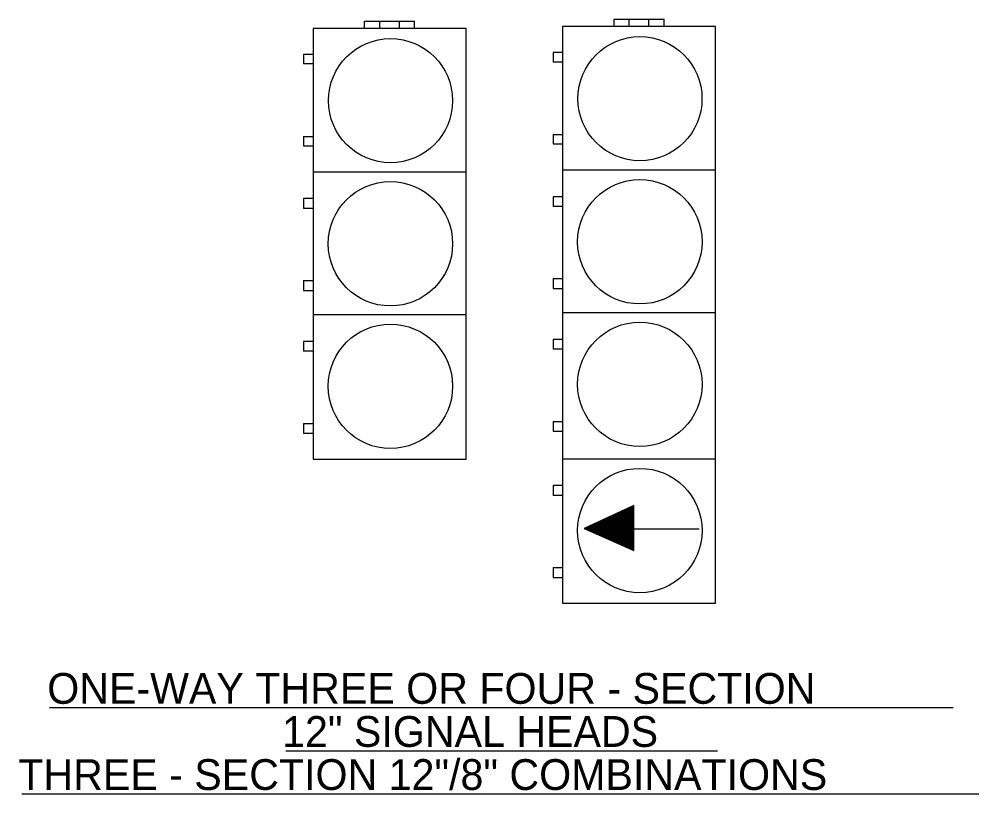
# Model space of a CAD drawing. Extents: x -1316.3 to -1303.1, y 2853.3 to 2863.3.
# Drawn here: x -1316.17 to -1313.052, y 2860.306 to 2862.823 of the extents above; entities that cross this region are included whole.
import ezdxf

# ---------------------------------------------------------------- set-up
doc = ezdxf.new("R2010")
doc.units = 0
for name, color, linetype in [('DETL-DIMS', 7, 'Continuous'), ('DETL-LINE', 7, 'Continuous'), ('DETL-TITL', 7, 'Continuous')]:
    doc.layers.add(name, color=color, linetype=linetype)

msp = doc.modelspace()

# ---------------------------------------------------------------- linework, layer by layer
at = {"layer": 'DETL-DIMS'}
for p, q in [((-1314.1736, 2861.2434), (-1314.3352, 2861.1682)), ((-1314.1856, 2861.1018), (-1314.1856, 2861.2378)), ((-1314.1832, 2861.1002), (-1314.1832, 2861.2386)), ((-1314.1808, 2861.0994), (-1314.1808, 2861.2402)), ((-1314.1784, 2861.0986), (-1314.1784, 2861.241)), ((-1314.176, 2861.097), (-1314.176, 2861.2426)), ((-1314.1736, 2861.0962), (-1314.1736, 2861.2434)), ((-1314.1736, 2861.0962), (-1314.1736, 2861.2434)), ((-1314.2528, 2861.1314), (-1314.2528, 2861.2066)), ((-1314.2504, 2861.1306), (-1314.2504, 2861.2074)), ((-1314.248, 2861.1298), (-1314.248, 2861.209)), ((-1314.2456, 2861.1282), (-1314.2456, 2861.2098)), ((-1314.2432, 2861.1274), (-1314.2432, 2861.2106)), ((-1314.2408, 2861.1266), (-1314.2408, 2861.2122)), ((-1314.2384, 2861.125), (-1314.2384, 2861.213)), ((-1314.236, 2861.1242), (-1314.236, 2861.2146)), ((-1314.2336, 2861.1234), (-1314.2336, 2861.2154)), ((-1314.2312, 2861.1218), (-1314.2312, 2861.2162)), ((-1314.2288, 2861.121), (-1314.2288, 2861.2178)), ((-1314.2264, 2861.1202), (-1314.2264, 2861.2186)), ((-1314.224, 2861.1186), (-1314.224, 2861.2202)), ((-1314.2216, 2861.1178), (-1314.2216, 2861.221)), ((-1314.2192, 2861.117), (-1314.2192, 2861.2218)), ((-1314.2168, 2861.1154), (-1314.2168, 2861.2234)), ((-1314.2144, 2861.1146), (-1314.2144, 2861.2242)), ((-1314.212, 2861.113), (-1314.212, 2861.2258)), ((-1314.2096, 2861.1122), (-1314.2096, 2861.2266)), ((-1314.2072, 2861.1114), (-1314.2072, 2861.2274)), ((-1314.2048, 2861.1106), (-1314.2048, 2861.229)), ((-1314.2024, 2861.109), (-1314.2024, 2861.2298)), ((-1314.2, 2861.1082), (-1314.2, 2861.2314)), ((-1314.1976, 2861.1066), (-1314.1976, 2861.2322)), ((-1314.1952, 2861.1058), (-1314.1952, 2861.233)), ((-1314.1928, 2861.105), (-1314.1928, 2861.2346)), ((-1314.1904, 2861.1034), (-1314.1904, 2861.2354)), ((-1314.188, 2861.1026), (-1314.188, 2861.237)), ((-1314.32, 2861.1618), (-1314.32, 2861.1754)), ((-1314.3176, 2861.1602), (-1314.3176, 2861.1762)), ((-1314.3152, 2861.1594), (-1314.3152, 2861.177)), ((-1314.3128, 2861.1586), (-1314.3128, 2861.1786)), ((-1314.3104, 2861.157), (-1314.3104, 2861.1794)), ((-1314.308, 2861.1562), (-1314.308, 2861.181)), ((-1314.3056, 2861.1554), (-1314.3056, 2861.1818)), ((-1314.3032, 2861.1538), (-1314.3032, 2861.1826)), ((-1314.3008, 2861.153), (-1314.3008, 2861.1842)), ((-1314.2984, 2861.1522), (-1314.2984, 2861.185)), ((-1314.296, 2861.1506), (-1314.296, 2861.1866)), ((-1314.2936, 2861.1498), (-1314.2936, 2861.1874)), ((-1314.2912, 2861.149), (-1314.2912, 2861.1882)), ((-1314.2888, 2861.1474), (-1314.2888, 2861.1898)), ((-1314.2864, 2861.1466), (-1314.2864, 2861.1906)), ((-1314.284, 2861.1458), (-1314.284, 2861.1922)), ((-1314.2816, 2861.1442), (-1314.2816, 2861.193)), ((-1314.2792, 2861.1434), (-1314.2792, 2861.1938)), ((-1314.2768, 2861.1426), (-1314.2768, 2861.1954)), ((-1314.2744, 2861.141), (-1314.2744, 2861.1962)), ((-1314.272, 2861.1402), (-1314.272, 2861.1978)), ((-1314.2696, 2861.1394), (-1314.2696, 2861.1986)), ((-1314.2672, 2861.1378), (-1314.2672, 2861.1994)), ((-1314.2648, 2861.137), (-1314.2648, 2861.201)), ((-1314.2624, 2861.1362), (-1314.2624, 2861.2018)), ((-1314.26, 2861.1346), (-1314.26, 2861.2034)), ((-1314.2576, 2861.1338), (-1314.2576, 2861.2042)), ((-1314.2552, 2861.133), (-1314.2552, 2861.205)), ((-1314.3352, 2861.1682), (-1314.1736, 2861.0962)), ((-1314.3344, 2861.1682), (-1314.3344, 2861.1682)), ((-1314.332, 2861.1666), (-1314.332, 2861.1698)), ((-1314.3296, 2861.1658), (-1314.3296, 2861.1706)), ((-1314.3272, 2861.165), (-1314.3272, 2861.1714)), ((-1314.3248, 2861.1634), (-1314.3248, 2861.173)), ((-1314.3224, 2861.1626), (-1314.3224, 2861.1738)), ((-1313.9608, 2861.1658), (-1314.3032, 2861.1658))]:
    msp.add_line(p, q, dxfattribs=at)
at = {"layer": 'DETL-LINE'}
for p, q in [((-1315.048, 2862.817), (-1314.8856, 2862.817)), ((-1315.048, 2862.793), (-1315.048, 2862.817)), ((-1314.9984, 2862.793), (-1314.9984, 2862.817)), ((-1314.9352, 2862.793), (-1314.9352, 2862.817)), ((-1314.8856, 2862.793), (-1314.8856, 2862.817)), ((-1314.4048, 2862.7994), (-1314.4048, 2860.925)), ((-1313.908, 2862.7994), (-1314.4048, 2862.7994)), ((-1314.2376, 2862.8234), (-1314.0752, 2862.8234)), ((-1314.2376, 2862.7994), (-1314.2376, 2862.8234)), ((-1314.188, 2862.7994), (-1314.188, 2862.8234)), ((-1314.1248, 2862.7994), (-1314.1248, 2862.8234)), ((-1314.0752, 2862.7994), (-1314.0752, 2862.8234)), ((-1313.908, 2860.925), (-1313.908, 2862.7994)), ((-1315.2152, 2862.793), (-1315.2152, 2861.3938)), ((-1314.7184, 2862.793), (-1315.2152, 2862.793)), ((-1314.7184, 2861.3938), (-1314.7184, 2862.793)), ((-1315.2152, 2862.709), (-1315.2464, 2862.709)), ((-1315.2464, 2862.709), (-1315.2464, 2862.6778)), ((-1314.4048, 2862.7154), (-1314.436, 2862.7154)), ((-1314.436, 2862.7154), (-1314.436, 2862.6842)), ((-1315.2152, 2862.6778), (-1315.2464, 2862.6778)), ((-1314.4048, 2862.6842), (-1314.436, 2862.6842)), ((-1315.2464, 2862.4426), (-1315.2152, 2862.4426)), ((-1315.2464, 2862.4426), (-1315.2464, 2862.4114)), ((-1314.436, 2862.449), (-1314.4048, 2862.449)), ((-1314.436, 2862.449), (-1314.436, 2862.4178)), ((-1315.2464, 2862.4114), (-1315.2152, 2862.4114)), ((-1314.436, 2862.4178), (-1314.4048, 2862.4178)), ((-1314.4048, 2862.3338), (-1313.9104, 2862.3338)), ((-1315.2152, 2862.3274), (-1314.7208, 2862.3274)), ((-1315.2464, 2862.2402), (-1315.2464, 2862.2082)), ((-1315.2152, 2862.2402), (-1315.2464, 2862.2402)), ((-1314.436, 2862.2466), (-1314.436, 2862.2146)), ((-1314.4048, 2862.2466), (-1314.436, 2862.2466)), ((-1315.2152, 2862.2082), (-1315.2464, 2862.2082)), ((-1314.4048, 2862.2146), (-1314.436, 2862.2146)), ((-1315.2464, 2861.9738), (-1315.2464, 2861.9418)), ((-1315.2464, 2861.9738), (-1315.2152, 2861.9738)), ((-1314.436, 2861.9802), (-1314.436, 2861.9482)), ((-1314.436, 2861.9802), (-1314.4048, 2861.9802)), ((-1315.2464, 2861.9418), (-1315.2152, 2861.9418)), ((-1314.436, 2861.9482), (-1314.4048, 2861.9482)), ((-1315.2152, 2861.8634), (-1314.7184, 2861.8634)), ((-1314.4048, 2861.8698), (-1313.908, 2861.8698)), ((-1315.2152, 2861.7762), (-1315.2464, 2861.7762)), ((-1315.2464, 2861.7762), (-1315.2464, 2861.7442)), ((-1314.4048, 2861.7826), (-1314.436, 2861.7826)), ((-1314.436, 2861.7826), (-1314.436, 2861.7506)), ((-1315.2152, 2861.7442), (-1315.2464, 2861.7442)), ((-1314.4048, 2861.7506), (-1314.436, 2861.7506)), ((-1315.2464, 2861.5098), (-1315.2152, 2861.5098)), ((-1315.2464, 2861.5098), (-1315.2464, 2861.4778)), ((-1314.436, 2861.5162), (-1314.4048, 2861.5162)), ((-1314.436, 2861.5162), (-1314.436, 2861.4842)), ((-1315.2464, 2861.4778), (-1315.2152, 2861.4778)), ((-1314.436, 2861.4842), (-1314.4048, 2861.4842)), ((-1315.2152, 2861.3938), (-1314.7184, 2861.3938)), ((-1314.4048, 2861.3946), (-1313.908, 2861.3946)), ((-1314.4048, 2861.3074), (-1314.436, 2861.3074)), ((-1314.436, 2861.3074), (-1314.436, 2861.2754)), ((-1314.4048, 2861.2754), (-1314.436, 2861.2754)), ((-1314.436, 2861.041), (-1314.4048, 2861.041)), ((-1314.436, 2861.041), (-1314.436, 2861.009)), ((-1314.436, 2861.009), (-1314.4048, 2861.009)), ((-1314.4048, 2860.925), (-1313.908, 2860.925))]:
    msp.add_line(p, q, dxfattribs=at)
for centre, radius in [((-1314.1535, 2862.565), 0.2016), ((-1314.9639, 2862.5586), 0.2016), ((-1314.1539, 2862.1), 0.2021), ((-1314.9643, 2862.0936), 0.2021), ((-1314.9643, 2861.6303), 0.2021), ((-1314.1539, 2861.6367), 0.2021), ((-1314.1539, 2861.1615), 0.2021)]:
    msp.add_circle(centre, radius, dxfattribs=at)
at = {"layer": 'DETL-TITL'}
for p, q in [((-1316.072, 2860.586), (-1313.1355, 2860.586)), ((-1315.3042, 2860.4459), (-1313.9011, 2860.4459)), ((-1316.1618, 2860.3059), (-1313.0525, 2860.3059))]:
    msp.add_line(p, q, dxfattribs=at)

# ---------------------------------------------------------------- texts
for s, p in [('ONE-WAY THREE OR FOUR - SECTION', (-1316.0794, 2860.5985)), ('12" SIGNAL HEADS', (-1315.3162, 2860.4585)), ('THREE - SECTION 12"/8" COMBINATIONS', (-1316.1735, 2860.3185))]:
    msp.add_text(s, height=0.1, dxfattribs=at).set_placement(p)

doc.saveas('drawing.dxf')
